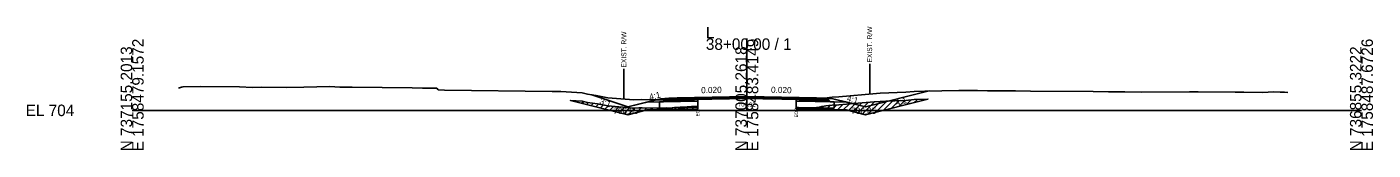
# Model space of a CAD drawing. Extents: x -26 to 4303, y -10 to 9577.
# Drawn here: x 1974.3 to 2302.8, y 7990.3 to 8020.4 of the extents above; entities that cross this region are included whole.
import ezdxf

# ---------------------------------------------------------------- set-up
doc = ezdxf.new("R2010")
doc.units = 0
for name, color, linetype in [('Default', 7, 'Continuous'), ('Exist CMT Pavement', 7, 'Continuous'), ('Old_Level_2', 7, 'Continuous'), ('Pattern 1', 7, 'Continuous'), ('Prop CMT Conc Surface', 7, 'Continuous'), ('Prop CMT Concrete Structures', 7, 'Continuous'), ('Prop CMT Pvmt Course 1', 7, 'Continuous'), ('Prop CMT Pvmt Course 1 CG', 7, 'Continuous'), ('Prop CMT Pvmt Course 1 Wedge', 7, 'Continuous'), ('Prop CMT Pvmt Course 2', 7, 'Continuous'), ('Prop CMT Pvmt Course 2 Wedge', 7, 'Continuous'), ('Prop CMT Pvmt Course 3', 7, 'Continuous'), ('Prop CMT Pvmt Surface', 7, 'Continuous'), ('Prop CMT Pvmt Surface Shoulder', 7, 'Continuous'), ('Prop CMT Pvmt Wedge Surface 1', 7, 'Continuous'), ('Prop CMT Pvmt Wedge Surface 2', 7, 'Continuous'), ('Prop CMT Pvmt Wedge Surface 3', 7, 'Continuous'), ('Prop CMT Shld Paved Course 1', 7, 'Continuous'), ('Prop CMT Shld Paved Course 2', 7, 'Continuous'), ('Prop CMT Shld Paved Course 3', 7, 'Continuous'), ('Prop CMT Slope Grass', 7, 'Continuous'), ('Prop CMT Subgrade Earthwork', 7, 'Continuous'), ('Prop Road Sect_ Recs - UC Shallow (Outline)', 7, 'Continuous'), ('Prop Shade Light', 7, 'Continuous'), ('Prop XS DDE Elevations', 7, 'Continuous'), ('Prop XS Ditch Standard Text', 7, 'Continuous'), ('Prop XS Hydro Elevations', 7, 'Continuous'), ('Prop XS SE Text', 7, 'Continuous'), ('Prop XS Side Slope Text', 7, 'Continuous'), ('Prop XS Wedging', 7, 'Continuous')]:
    doc.layers.add(name, color=color, linetype=linetype)

msp = doc.modelspace()

# ---------------------------------------------------------------- linework, layer by layer
at = {"layer": 'Exist CMT Pavement'}
for points in [[(2150, 8003.39), (2133, 8003.05)], [(2150, 8003.39), (2167, 8003.05)]]:
    msp.add_lwpolyline(points, dxfattribs=at)
at = {"layer": 'Old_Level_2'}
for p, q in [((2150, 8000), (2150, 8017.56)), ((2150, 8000), (2150, 8017.56)), ((2000, 8000), (2150, 8000)), ((2000, 8000), (2150, 8000)), ((2150, 8000), (2300, 8000)), ((2150, 8000), (2300, 8000))]:
    msp.add_line(p, q, dxfattribs=at)
at = {"layer": 'Pattern 1'}
for p, q in [((2107.5, 8002.31), (2107.59, 8002.4)), ((2108.63, 8002.02), (2108.92, 8002.31)), ((2109.76, 8001.74), (2110.19, 8002.17)), ((2110.89, 8001.46), (2111.35, 8001.91)), ((2112.03, 8001.17), (2112.57, 8001.72)), ((2113.16, 8000.89), (2113.79, 8001.52)), ((2114.29, 8000.61), (2114.97, 8001.29)), ((2115.42, 8000.33), (2116.16, 8001.06)), ((2116.55, 8000.04), (2117.46, 8000.95)), ((2117.68, 7999.76), (2118.77, 8000.84)), ((2118.81, 7999.48), (2120.07, 8000.73)), ((2119.95, 7999.19), (2121.37, 8000.62)), ((2121.13, 7998.96), (2122.71, 8000.55)), ((2123.01, 7999.43), (2124.18, 8000.6)), ((2124.9, 7999.91), (2125.58, 8000.59)), ((2126.53, 8000.13), (2126.98, 8000.57)), ((2127.98, 8000.16), (2128.37, 8000.55)), ((2129.42, 8000.19), (2129.8, 8000.57)), ((2130.87, 8000.21), (2131.18, 8000.53)), ((2132.31, 8000.24), (2132.76, 8000.69)), ((2133.75, 8000.27), (2134.26, 8000.78)), ((2135.2, 8000.3), (2135.76, 8000.87)), ((2136.64, 8000.33), (2137.26, 8000.95)), ((2162.45, 8000.35), (2162.79, 8000.68)), ((2163.84, 8000.32), (2164.14, 8000.62)), ((2165.22, 8000.29), (2165.49, 8000.55)), ((2166.61, 8000.26), (2167.01, 8000.66)), ((2168, 8000.24), (2168.74, 8000.98)), ((2169.38, 8000.21), (2170.37, 8001.2)), ((2170.77, 8000.18), (2171.89, 8001.3)), ((2172.16, 8000.15), (2173.42, 8001.41)), ((2173.54, 8000.13), (2174.96, 8001.54)), ((2174.81, 7999.98), (2176.51, 8001.68)), ((2175.94, 7999.7), (2178.05, 8001.81)), ((2177.07, 7999.41), (2179.6, 8001.94)), ((2178.21, 7999.13), (2181.15, 8002.07)), ((2179.56, 7999.07), (2182.64, 8002.15)), ((2181.45, 7999.54), (2184.14, 8002.23)), ((2183.33, 8000.01), (2185.61, 8002.29)), ((2185.22, 8000.49), (2187.08, 8002.35)), ((2187.1, 8000.96), (2188.55, 8002.41)), ((2188.99, 8001.43), (2190.11, 8002.55)), ((2190.87, 8001.9), (2191.62, 8002.65)), ((2192.76, 8002.37), (2193.08, 8002.69))]:
    msp.add_line(p, q, dxfattribs=at)
for points in [[(2121, 7998.93), (2106.95, 8002.44), (2109.85, 8002.25), (2111.1, 8001.95), (2113.56, 8001.56), (2116.11, 8001.07), (2122.43, 8000.53), (2123.61, 8000.58), (2124.44, 8000.61), (2128.09, 8000.55), (2128.69, 8000.55), (2130.35, 8000.58), (2130.73, 8000.55), (2131.5, 8000.51), (2132.33, 8000.67), (2133.74, 8000.75), (2135.42, 8000.85), (2136.48, 8000.91), (2138.01, 8001), (2138.01, 8000.36), (2128.46, 8000.17), (2125.72, 8000.11)], [(2174.28, 8000.11), (2179, 7998.93), (2194.19, 8002.73), (2190.83, 8002.62), (2188.83, 8002.42), (2186.1, 8002.31), (2183.91, 8002.23), (2181.11, 8002.07), (2176.21, 8001.65), (2172.44, 8001.33), (2170.8, 8001.25), (2170.03, 8001.16), (2169.32, 8001.07), (2168.85, 8001), (2168.3, 8000.9), (2167.75, 8000.8), (2167, 8000.66), (2166.22, 8000.52), (2163.78, 8000.64), (2162.63, 8000.69), (2162.06, 8000.71), (2162.06, 8000.35), (2171.3, 8000.17)]]:
    msp.add_lwpolyline(points, close=True, dxfattribs=at)
at = {"layer": 'Prop CMT Conc Surface'}
for points in [[(2138.01, 8002.9), (2133, 8002.8)], [(2133, 8002.8), (2133, 8002.59)], [(2133, 8002.59), (2138.01, 8002.69)], [(2138.01, 8002.69), (2138.01, 8002.9)], [(2162.06, 8002.69), (2162.06, 8002.9)], [(2162.06, 8002.9), (2167, 8002.8)], [(2167, 8002.59), (2162.06, 8002.69)], [(2167, 8002.8), (2167, 8002.59)]]:
    msp.add_lwpolyline(points, dxfattribs=at)
at = {"layer": 'Prop CMT Concrete Structures'}
for points in [[(2150, 8003.27), (2138.01, 8003.03)], [(2150, 8003.27), (2162.06, 8003.03)], [(2133, 8002.8), (2133, 8003.05)], [(2138.01, 8002.9), (2133, 8002.8)], [(2138.01, 8003.03), (2138.01, 8002.9)], [(2162.06, 8003.03), (2162.06, 8002.9)], [(2162.06, 8002.9), (2167, 8002.8)], [(2167, 8002.8), (2167, 8003.05)]]:
    msp.add_lwpolyline(points, dxfattribs=at)
at = {"layer": 'Prop CMT Pvmt Course 1'}
for points in [[(2138.01, 8002.69), (2133, 8002.59)], [(2133, 8002.59), (2133, 8002.26)], [(2133, 8002.26), (2138.01, 8002.36)], [(2138.01, 8002.36), (2138.01, 8002.69)], [(2162.06, 8002.69), (2167, 8002.59)], [(2162.06, 8002.36), (2162.06, 8002.69)], [(2167, 8002.26), (2162.06, 8002.36)], [(2167, 8002.59), (2167, 8002.26)]]:
    msp.add_lwpolyline(points, dxfattribs=at)
at = {"layer": 'Prop CMT Pvmt Course 1 Wedge'}
for points in [[(2150, 8002.92), (2149.13, 8002.9), (2149.01, 8002.91), (2148.78, 8002.91)], [(2148.78, 8002.91), (2149.01, 8002.91)], [(2149.01, 8002.91), (2149.13, 8002.92), (2150, 8002.93)], [(2150, 8002.93), (2150, 8002.92)], [(2150, 8002.93), (2150.25, 8002.93), (2151.43, 8002.91), (2151.51, 8002.9), (2151.8, 8002.9), (2153.77, 8002.86)], [(2153.77, 8002.86), (2151.8, 8002.89), (2151.51, 8002.89), (2151.43, 8002.9), (2150.25, 8002.92), (2150, 8002.92)]]:
    msp.add_lwpolyline(points, dxfattribs=at)
at = {"layer": 'Prop CMT Pvmt Course 2'}
for points in [[(2133, 8003.05), (2131, 8003.01), (2130.74, 8002.76)], [(2130.74, 8002.76), (2133, 8002.8)], [(2133, 8002.8), (2133, 8003.05)], [(2167, 8003.05), (2169, 8003.01), (2169.26, 8002.76)], [(2167, 8002.8), (2167, 8003.05)], [(2169.26, 8002.76), (2167, 8002.8)]]:
    msp.add_lwpolyline(points, dxfattribs=at)
at = {"layer": 'Prop CMT Pvmt Course 2 Wedge'}
msp.add_line((2121, 8000.85), (2112.2, 8003.79), dxfattribs=at)
for points in [[(2169, 8003.01), (2171, 8002.85), (2179, 8000.85), (2194.52, 8004.73)], [(2131, 8003.01), (2129, 8002.85), (2121, 8000.85)]]:
    msp.add_lwpolyline(points, dxfattribs=at)
at = {"layer": 'Prop CMT Pvmt Course 3'}
for points in [[(2133, 8002.8), (2130.74, 8002.76), (2130.53, 8002.54)], [(2130.53, 8002.54), (2133, 8002.59)], [(2133, 8002.59), (2133, 8002.8)], [(2167, 8002.8), (2169.26, 8002.76), (2169.47, 8002.54)], [(2167, 8002.59), (2167, 8002.8)], [(2169.47, 8002.54), (2167, 8002.59)]]:
    msp.add_lwpolyline(points, dxfattribs=at)
at = {"layer": 'Prop CMT Pvmt Surface'}
for points in [[(2150, 8003.14), (2133, 8002.8)], [(2150, 8003.14), (2167, 8002.8)], [(2133, 8002.8), (2133, 8003.05)], [(2167, 8002.8), (2167, 8003.05)]]:
    msp.add_lwpolyline(points, dxfattribs=at)
at = {"layer": 'Prop CMT Pvmt Surface Shoulder'}
for points in [[(2138.01, 8003), (2138.07, 8003), (2138.86, 8002.99), (2138.87, 8002.99), (2138.96, 8002.99), (2139.06, 8002.99), (2141.51, 8002.96), (2142.07, 8002.96), (2144.01, 8002.96), (2144.5, 8002.96), (2146.51, 8002.94), (2146.93, 8002.94), (2149.01, 8002.91), (2149.13, 8002.9), (2150, 8002.92)], [(2150, 8002.92), (2150.25, 8002.92), (2151.43, 8002.9), (2151.51, 8002.89), (2151.8, 8002.89), (2154.01, 8002.85), (2154.23, 8002.85), (2156.51, 8002.83), (2156.66, 8002.82), (2159.02, 8002.76), (2159.13, 8002.76), (2160.61, 8002.72), (2161.69, 8002.7), (2162.02, 8002.71), (2162.06, 8002.71)]]:
    msp.add_lwpolyline(points, dxfattribs=at)
at = {"layer": 'Prop CMT Pvmt Wedge Surface 1'}
for p, q in [((2133.02, 8002.14), (2125.53, 8001.99)), ((2138.01, 8002.24), (2133.02, 8002.14)), ((2162.06, 8002.23), (2166.98, 8002.14)), ((2166.98, 8002.14), (2174.47, 8001.99))]:
    msp.add_line(p, q, dxfattribs=at)
for points in [[(2138.01, 8002.24), (2138.01, 8003)], [(2162.06, 8002.23), (2162.06, 8002.71)]]:
    msp.add_lwpolyline(points, dxfattribs=at)
at = {"layer": 'Prop CMT Pvmt Wedge Surface 2'}
for points in [[(2138.01, 8003.03), (2138.07, 8003.03), (2138.86, 8003.04), (2138.87, 8003.04), (2138.96, 8003.05), (2139.06, 8003.05), (2141.51, 8003.1), (2142.07, 8003.11), (2144.01, 8003.15), (2144.5, 8003.16), (2146.51, 8003.2), (2146.93, 8003.21), (2149.01, 8003.25), (2149.13, 8003.25), (2150, 8003.27)], [(2150, 8003.14), (2149.13, 8003.12), (2149.01, 8003.12), (2146.93, 8003.08), (2146.51, 8003.07), (2144.5, 8003.03), (2144.01, 8003.02), (2142.07, 8002.98), (2141.51, 8002.97), (2141.13, 8002.96), (2139.06, 8002.99), (2138.96, 8002.99), (2138.87, 8002.99), (2138.86, 8002.99), (2138.07, 8003), (2138.01, 8003)], [(2150, 8003.27), (2150, 8003.14)], [(2150, 8003.27), (2150.25, 8003.26), (2151.43, 8003.24), (2151.51, 8003.24), (2151.8, 8003.23), (2154.01, 8003.19), (2154.23, 8003.18), (2156.51, 8003.14), (2156.66, 8003.13), (2159.02, 8003.09), (2159.13, 8003.08), (2160.61, 8003.05), (2161.69, 8003.03), (2162.02, 8003.03), (2162.06, 8003.03)], [(2162.06, 8002.9), (2162.02, 8002.9), (2161.69, 8002.91), (2160.61, 8002.93), (2159.13, 8002.96), (2159.02, 8002.96), (2156.66, 8003.01), (2156.51, 8003.01), (2154.23, 8003.06), (2154.01, 8003.06), (2151.8, 8003.11), (2151.51, 8003.11), (2151.43, 8003.11), (2150.25, 8003.14), (2150, 8003.14)], [(2138.01, 8003), (2138.01, 8003.03)], [(2162.06, 8003.03), (2162.06, 8002.9)]]:
    msp.add_lwpolyline(points, dxfattribs=at)
at = {"layer": 'Prop CMT Pvmt Wedge Surface 3'}
for points in [[(2141.51, 8002.97), (2142.07, 8002.98), (2144.01, 8003.02), (2144.5, 8003.03), (2146.51, 8003.07), (2146.93, 8003.08), (2149.01, 8003.12), (2149.13, 8003.12), (2150, 8003.14)], [(2150, 8003.14), (2150, 8002.93)], [(2150, 8003.14), (2150.25, 8003.14), (2151.43, 8003.11), (2151.51, 8003.11), (2151.8, 8003.11), (2154.01, 8003.06), (2154.23, 8003.06), (2156.51, 8003.01), (2156.66, 8003.01), (2159.02, 8002.96), (2159.13, 8002.96), (2160.61, 8002.93), (2161.69, 8002.91), (2162.02, 8002.9), (2162.06, 8002.9)], [(2141.13, 8002.96), (2141.51, 8002.97)], [(2150, 8002.93), (2149.13, 8002.92), (2149.01, 8002.91), (2148.78, 8002.91), (2146.93, 8002.94), (2146.51, 8002.94), (2144.5, 8002.96), (2144.01, 8002.96), (2142.07, 8002.96), (2141.51, 8002.96), (2141.13, 8002.96)], [(2162.06, 8002.71), (2162.02, 8002.71), (2161.69, 8002.7), (2160.61, 8002.72), (2159.13, 8002.76), (2159.02, 8002.76), (2156.66, 8002.82), (2156.51, 8002.83), (2154.23, 8002.85), (2154.01, 8002.85), (2153.77, 8002.86), (2151.8, 8002.9), (2151.51, 8002.9), (2151.43, 8002.91), (2150.25, 8002.93), (2150, 8002.93)], [(2162.06, 8002.9), (2162.06, 8002.71)]]:
    msp.add_lwpolyline(points, dxfattribs=at)
at = {"layer": 'Prop CMT Shld Paved Course 1'}
for points in [[(2133, 8002.59), (2133, 8003.05)], [(2150, 8002.93), (2133, 8002.59)], [(2150, 8002.93), (2167, 8002.59)], [(2167, 8002.59), (2167, 8003.05)]]:
    msp.add_lwpolyline(points, dxfattribs=at)
at = {"layer": 'Prop CMT Shld Paved Course 2'}
for points in [[(2133, 8003.05), (2131, 8003.01)], [(2167, 8003.05), (2169, 8003.01)]]:
    msp.add_lwpolyline(points, dxfattribs=at)
at = {"layer": 'Prop CMT Shld Paved Course 3'}
for points in [[(2150, 8003.39), (2133, 8003.05)], [(2138.01, 8003.03), (2150, 8003.27)], [(2150, 8003.14), (2150, 8003.39)], [(2150, 8003.39), (2167, 8003.05)], [(2150, 8003.27), (2150, 8003.14), (2150, 8003.14)], [(2162.06, 8003.03), (2150, 8003.27)], [(2133, 8003.05), (2133, 8002.8)], [(2133, 8002.8), (2138.01, 8002.9)], [(2138.01, 8002.9), (2138.01, 8003.03)], [(2162.06, 8002.9), (2162.06, 8003.03)], [(2167, 8002.8), (2162.06, 8002.9)], [(2167, 8003.05), (2167, 8002.8)]]:
    msp.add_lwpolyline(points, dxfattribs=at)
at = {"layer": 'Prop CMT Slope Grass'}
msp.add_lwpolyline([(2011.28, 8005.38), (2012.06, 8005.67), (2012.4, 8005.74), (2016.75, 8005.83), (2026.15, 8005.72), (2029.39, 8005.61), (2031.51, 8005.62), (2037.72, 8005.59), (2041.91, 8005.63), (2048.21, 8005.85), (2050.69, 8005.62), (2053.66, 8005.63), (2068.36, 8005.46), (2070.85, 8005.44), (2074.33, 8005.44), (2074.69, 8005), (2076.19, 8004.95), (2102.48, 8004.62), (2103.67, 8004.6), (2104.61, 8004.6), (2109.85, 8004.25), (2111.1, 8003.95), (2113.25, 8003.62), (2116.11, 8003.07), (2122.42, 8002.53), (2124.24, 8002.61), (2128.39, 8002.54), (2130.36, 8002.58), (2130.8, 8002.54), (2131.5, 8002.52), (2132.32, 8002.67), (2138.07, 8003), (2138.87, 8002.99), (2141.51, 8002.96), (2142.07, 8002.96), (2144.01, 8002.96), (2144.5, 8002.96), (2146.51, 8002.94), (2148.64, 8002.91), (2149.13, 8002.9), (2150.25, 8002.92), (2151.8, 8002.89), (2154.23, 8002.85), (2156.66, 8002.82), (2159.13, 8002.76), (2160.61, 8002.72), (2161.69, 8002.7), (2162.08, 8002.71), (2162.88, 8002.68), (2166.22, 8002.52), (2168.92, 8003.01), (2170.16, 8003.17), (2170.8, 8003.25), (2172.44, 8003.33), (2181.61, 8004.11), (2182.56, 8004.17), (2188.83, 8004.42), (2190.83, 8004.62), (2193.44, 8004.72), (2201.78, 8004.82), (2202.98, 8004.83), (2204.74, 8004.83), (2206.32, 8004.86), (2208.76, 8004.79), (2215.61, 8004.8), (2219.26, 8004.66), (2234.5, 8004.59), (2238.26, 8004.54), (2242.24, 8004.51), (2246.21, 8004.45), (2258.07, 8004.51), (2259.41, 8004.55), (2260.15, 8004.5), (2269.17, 8004.42), (2271.29, 8004.44), (2275.94, 8004.33), (2278.5, 8004.49), (2280.13, 8004.44), (2281.25, 8004.46), (2282.07, 8004.39)], dxfattribs=at)
at = {"layer": 'Prop CMT Subgrade Earthwork'}
for points in [[(2133, 8002.59), (2130.53, 8002.54), (2130.03, 8002.53), (2129.69, 8002.19)], [(2129.69, 8002.19), (2133, 8002.26)], [(2133, 8002.26), (2133, 8002.59)], [(2167, 8002.59), (2169.47, 8002.54), (2169.97, 8002.53), (2170.31, 8002.19)], [(2167, 8002.26), (2167, 8002.59)], [(2170.31, 8002.19), (2167, 8002.26)]]:
    msp.add_lwpolyline(points, dxfattribs=at)
at = {"layer": 'Prop Road Sect_ Recs - UC Shallow (Outline)'}
for p, q in [((2128.69, 8002.05), (2129.69, 8002.07)), ((2129.69, 8002.07), (2138.01, 8002.24))]:
    msp.add_line(p, q, dxfattribs=at)
for points in [[(2138.04, 8000.74), (2128.72, 8000.55), (2128.69, 8002.05), (2138.01, 8002.24)], [(2162.06, 8002.23), (2162.03, 8000.73), (2171.28, 8000.55), (2171.31, 8002.05)]]:
    msp.add_lwpolyline(points, close=True, dxfattribs=at)
at = {"layer": 'Prop Shade Light'}
for p, q in [((2129.69, 8002.07), (2128.69, 8002.05)), ((2128.69, 8002.05), (2128.72, 8000.55)), ((2128.72, 8000.55), (2138.04, 8000.74)), ((2138.04, 8000.74), (2138.01, 8002.24)), ((2162.06, 8002.23), (2162.03, 8000.73)), ((2162.03, 8000.73), (2171.28, 8000.55)), ((2171.31, 8002.05), (2170.31, 8002.07)), ((2171.28, 8000.55), (2171.31, 8002.05))]:
    msp.add_line(p, q, dxfattribs=at)
for points in [[(2138.01, 8002.24), (2133, 8002.14), (2129.69, 8002.07)], [(2170.31, 8002.07), (2167, 8002.14), (2162.06, 8002.23)]]:
    msp.add_lwpolyline(points, dxfattribs=at)
at = {"layer": 'Prop XS DDE Elevations'}
for points in [[(2124.24, 8002.61), (2127.79, 8002.55), (2125.53, 8001.99), (2121, 8000.85), (2112.2, 8003.79), (2113.25, 8003.62), (2116.11, 8003.07), (2122.42, 8002.53)], [(2170.16, 8003.17), (2170.8, 8003.25), (2172.44, 8003.33), (2181.61, 8004.11), (2182.56, 8004.17), (2188.83, 8004.42), (2190.83, 8004.62), (2193.44, 8004.72), (2194.52, 8004.73), (2179, 8000.85), (2174.47, 8001.99), (2171, 8002.85), (2169, 8003.01), (2168.92, 8003.01)], [(2128.39, 8002.54), (2130.36, 8002.58), (2130.8, 8002.54), (2131.5, 8002.52), (2132.32, 8002.67), (2138.01, 8003), (2138.01, 8002.24), (2133.02, 8002.14), (2125.53, 8001.99), (2127.79, 8002.55)], [(2138.07, 8003), (2138.87, 8002.99), (2138.86, 8002.99)], [(2138.87, 8002.99), (2138.96, 8002.99), (2139.06, 8002.99), (2141.51, 8002.96)], [(2146.51, 8002.94), (2146.93, 8002.94), (2149.01, 8002.91), (2149.13, 8002.9), (2148.64, 8002.91)], [(2151.43, 8002.9), (2151.8, 8002.89), (2151.51, 8002.89)], [(2154.01, 8002.85), (2154.23, 8002.85), (2151.8, 8002.89)], [(2156.51, 8002.83), (2156.66, 8002.82), (2154.23, 8002.85)], [(2159.02, 8002.76), (2159.13, 8002.76), (2156.66, 8002.82)], [(2162.02, 8002.71), (2162.06, 8002.71), (2161.69, 8002.7)], [(2169, 8003.01), (2171, 8002.85), (2174.47, 8001.99), (2166.98, 8002.14), (2162.06, 8002.23), (2162.06, 8002.71), (2162.08, 8002.71), (2162.88, 8002.68), (2166.22, 8002.52), (2168.92, 8003.01)]]:
    msp.add_lwpolyline(points, close=True, dxfattribs=at)
at = {"layer": 'Prop XS Ditch Standard Text'}
for p, q in [((2120, 8010.14), (2120, 8002.74)), ((2180, 8011.37), (2180, 8003.97)), ((2138.01, 8003), (2138.01, 8000.95)), ((2162.06, 8002.71), (2162.06, 8000.66))]:
    msp.add_line(p, q, dxfattribs=at)
at = {"layer": 'Prop XS Wedging'}
for p, q in [((2138.01, 8003), (2138.01, 8003.3)), ((2148.98, 8003.12), (2148.78, 8002.91)), ((2148.78, 8002.91), (2148.98, 8003.12)), ((2148.98, 8003.12), (2148.78, 8002.91)), ((2148.98, 8003.12), (2150, 8003.14)), ((2150, 8003.14), (2150, 8003.14)), ((2150, 8003.14), (2150, 8003.14)), ((2150, 8003.14), (2153.41, 8003.07)), ((2153.41, 8003.07), (2153.61, 8002.86)), ((2153.41, 8003.07), (2153.61, 8002.86)), ((2153.61, 8002.86), (2153.41, 8003.07)), ((2162.06, 8002.71), (2162.06, 8003.28)), ((2138.01, 8003.03), (2138.01, 8003)), ((2138.01, 8003), (2138.07, 8003)), ((2159.13, 8002.76), (2160.61, 8002.72)), ((2160.61, 8002.72), (2161.69, 8002.7)), ((2162.06, 8002.71), (2162.06, 8003.03))]:
    msp.add_line(p, q, dxfattribs=at)
for points in [[(2150, 8003.27), (2133, 8002.93)], [(2150, 8003.27), (2150, 8003.27), (2138.01, 8003.03)], [(2150, 8003.14), (2148.98, 8003.12)], [(2150, 8003.14), (2150, 8003.14), (2148.98, 8003.12)], [(2150, 8003.27), (2167, 8002.93)], [(2162.06, 8003.03), (2150, 8003.27), (2150, 8003.27)], [(2150, 8003.14), (2153.41, 8003.07)], [(2150, 8003.14), (2150, 8003.14)], [(2150, 8003.14), (2150, 8003.14)], [(2153.41, 8003.07), (2150, 8003.14), (2150, 8003.14)], [(2138.07, 8003), (2138.86, 8002.99), (2138.87, 8002.99), (2138.96, 8002.99), (2139.06, 8002.99), (2141.51, 8002.96)], [(2141.51, 8002.96), (2142.07, 8002.96), (2144.01, 8002.96), (2144.5, 8002.96)], [(2144.5, 8002.96), (2146.51, 8002.94), (2146.93, 8002.94), (2148.78, 8002.91)], [(2148.78, 8002.91), (2149.01, 8002.91), (2149.13, 8002.9), (2150, 8002.92)], [(2150, 8002.92), (2150.25, 8002.92), (2151.43, 8002.9), (2151.44, 8002.9)], [(2151.44, 8002.9), (2151.51, 8002.89), (2151.8, 8002.89), (2153.61, 8002.86)], [(2153.61, 8002.86), (2154.01, 8002.86), (2154.23, 8002.85)], [(2154.23, 8002.85), (2156.51, 8002.83), (2156.66, 8002.82)], [(2156.66, 8002.82), (2159.02, 8002.76), (2159.13, 8002.76)], [(2161.69, 8002.7), (2162.02, 8002.71), (2162.06, 8002.71)]]:
    msp.add_lwpolyline(points, dxfattribs=at)

# ---------------------------------------------------------------- texts
at = {"layer": 'Default'}
msp.add_text('-', height=0.0001, dxfattribs=at).set_placement((2000, 8000))
at = {"layer": 'Old_Level_2'}
for s, p in [('L', (2140, 8017.56)), ('L', (2140, 8017.56)), ('38+00.00 / 1', (2140, 8014.76)), ('38+00.00 / 1', (2140, 8014.76)), ('EL 704', (1974, 7998.6)), ('EL 704', (1974, 7998.6))]:
    msp.add_text(s, height=2.8, dxfattribs=at).set_placement(p)
for s, p in [('E 1758479.1572', (2002.8, 7990)), ('E 1758479.1572', (2002.8, 7990)), ('E 1758483.4149', (2152.8, 7990)), ('E 1758483.4149', (2152.8, 7990)), ('E 1758487.6726', (2302.8, 7990)), ('E 1758487.6726', (2302.8, 7990)), ('N 737155.2013', (2000, 7990)), ('N 737155.2013', (2000, 7990)), ('N 737005.2618', (2150, 7990)), ('N 737005.2618', (2150, 7990)), ('N 736855.3222', (2300, 7990)), ('N 736855.3222', (2300, 7990))]:
    msp.add_text(s, height=2.8, rotation=90, dxfattribs=at).set_placement(p)
at = {"layer": 'Prop CMT Pvmt Course 1 CG'}
msp.add_text('706.92', height=1, dxfattribs=at).set_placement((2147.89, 8000.92))
at = {"layer": 'Prop XS Ditch Standard Text'}
for s, height, p in [('EXIST. R/W', 1.181, (2180.59, 8011.68)), ('EXIST. R/W', 1.181, (2120.59, 8010.44)), ('EOP', 0.787, (2138.41, 7998.55)), ('EOP', 0.787, (2162.45, 7998.26))]:
    msp.add_text(s, height=height, rotation=90, dxfattribs=at).set_placement(p)
at = {"layer": 'Prop XS Hydro Elevations'}
for p in [(2117.4, 7999.14), (2175.46, 7999.14)]:
    msp.add_text('706.85', height=1.5, dxfattribs=at).set_placement(p)
at = {"layer": 'Prop XS SE Text'}
for rotation, p in [(1.1458, (2138.86, 8004.17)), (358.8542, (2155.9, 8004.27))]:
    msp.add_text('0.020', height=1.5, rotation=rotation, dxfattribs=at).set_placement(p)
at = {"layer": 'Prop XS Side Slope Text'}
for s, rotation, p in [('4:1', 14.0362, (2126.37, 8002.49)), ('4:1', 345.9638, (2174.28, 8002.29)), ('4:1', 14.0362, (2186.48, 8001.11)), ('3:1', 339.8916, (2113.92, 8001.64))]:
    msp.add_text(s, height=1.5, rotation=rotation, dxfattribs=at).set_placement(p)

doc.saveas('drawing.dxf')
